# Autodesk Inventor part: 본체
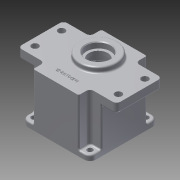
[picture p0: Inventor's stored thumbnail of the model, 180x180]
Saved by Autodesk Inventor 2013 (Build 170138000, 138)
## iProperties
Created: 2015-07
Part Number: 본체
Material: 알루미늄 6061
Document SubType Name: Modeling
Designer: user
Density: 1 g/cm^3
Author: user
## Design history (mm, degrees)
sketch "스케치1"
  geometry: L1 (-45, 45)-(45, 45); L2 (45, 45)-(45, -45); L3 (45, -45)-(-45, -45); L4 (-45, -45)-(-45, 45); 3 further points
  constraints: 8 end point, 2 midpoint, 2 parallel, 1 horizontal, 1 horizontal alignment, 1 perpendicular, 1 vertical alignment
  dimensions: "d0" = 90 distance of L1.start L1.end; "d2" = 90 distance of L1.end L2.end
extrude "돌출1" new body sketch "스케치1" distance "d3" = 7; taper "d4" = 0 deg
sketch "스케치2"
  geometry: L1 (45, 45)-(-45, 45) reference; L2 (-45, 45)-(-45, -45) reference; L3 (-45, -45)-(45, -45) reference; L4 (45, -45)-(45, 45) reference; L5 (-30, 45)-(30, 45); L6 (30, 45)-(30, -45); L7 (30, -45)-(-30, -45); L8 (-30, -45)-(-30, 45); L9 (-45, 30)-(45, 30); L10 (45, 30)-(45, -30); L11 (45, -30)-(-45, -30); L12 (-45, -30)-(-45, 30); 4 further points
  constraints: 16 end point, 4 parallel, 4 point on line, 3 midpoint, 2 horizontal, 2 perpendicular, 2 vertical alignment, 1 horizontal alignment
  dimensions: "d5" = 60 distance of L5.start L5.end; "d7" = 60 distance of L11.end L9.start
extrude "돌출2" join sketch "스케치2" distance "d8" = 63; taper "d9" = 0 deg
sketch "스케치3"
  geometry: L1 (-65, 30)-(65, 30); L2 (65, 30)-(65, -30); L3 (65, -30)-(-65, -30); L4 (-65, -30)-(-65, 30); 3 further points
  constraints: 8 end point, 2 midpoint, 2 parallel, 1 horizontal, 1 horizontal alignment, 1 perpendicular, 1 vertical alignment
  dimensions: "d10" = 60 distance of L3.end L1.start; "d12" = 130 distance of L1.start L1.end
extrude "돌출3" join sketch "스케치3" distance "d13" = 12; taper "d14" = 0 deg
fillet "모깎기1" dims "d15" = 5
sketch "스케치4"
  geometry: L1 (-35, -30)-(-65, -30) reference; L2 (0, 0)-(0, 9.418); L3 (0, 0)-(20.166, 0); C1 r 4.5 at (55, 17.5); C2 r 4.5 at (-55, 17.5); C3 r 4.5 at (-55, -17.5); C4 r 4.5 at (55, -17.5)
  constraints: 4 centre point, 4 end point, 3 symmetric about line, 2 perpendicular, 3 other
  dimensions: "d16" = 9 diameter of C1; "d17" = 110 diameter of C1.centre L2; "d18" = 35 diameter of C1.centre L3
extrude "돌출4" cut sketch "스케치4" distance "d19" = 12; taper "d20" = 0 deg
sketch "스케치5"
  geometry: L1 (45, -45)-(45, 45) reference; L2 (0, 0)-(0, 11.26); L3 (0, 0)-(11.158, 0); C1 r 3.5 at (37, 37); C2 r 3.5 at (-37, 37); C3 r 3.5 at (-37, -37); C4 r 3.5 at (37, -37)
  constraints: 4 centre point, 4 end point, 3 symmetric about line, 1 parallel, 1 perpendicular, 3 other
  dimensions: "d21" = 7 diameter of C1; "d22" = 74 diameter of C1.centre L2; "d23" = 74 diameter of C1.centre L3
extrude "돌출5" cut sketch "스케치5" distance "d24" = 12; taper "d25" = 0 deg
sketch "스케치6"
  geometry: C1 r 40 at (0, 0); 1 further point
  constraints: 1 centre point, 1 coincident
  dimensions: "d26" = 80 diameter of C1
extrude "돌출6" cut sketch "스케치6" distance "d27" = 9; taper "d28" = 0 deg
sketch "스케치7"
  geometry: C1 r 40 at (0, 0) reference; C2 r 39 at (0, 0)
  constraints: 1 centre point, 1 coincident
  dimensions: "d29" = 78 diameter of C2
extrude "돌출7" cut sketch "스케치7" distance "d30" = 52; taper "d31" = 0 deg
sketch "스케치8"
  geometry: L1 (0, 0)-(13.503, 0); L2 (0, 0)-(0, 6.492); L3 (24.749, 24.749)-(-24.749, -24.749); L4 (-24.749, 24.749)-(24.749, -24.749); C1 r 40 at (0, 0) reference; A1 r 39 centre (0, 0) between (21.134, 32.777) and (32.777, 21.134) reference; A2 r 4 centre (24.749, 24.749) between (21.809, 27.462) and (27.462, 21.809); A3 r 3.5 centre (29.836, 19.238) between (32.777, 21.134) and (27.412, 21.762); A4 r 3.5 centre (19.238, 29.836) between (21.762, 27.412) and (21.134, 32.777); 1 further point
  constraints: 10 point on circle, 8 end point, 3 centre point, 3 coincident, 2 midpoint, 2 tangent, 1 horizontal, 1 perpendicular, 1 symmetric about line, 1 other
  dimensions: "d33" = 45 deg angle of L3 L2; "d35" = 45 deg angle of L4 L2; "d37" = 8 diameter of A2; "d38" = 7 diameter of A3
extrude "돌출8" join sketch "스케치8" distance "d39" = 52; taper "d40" = 0 deg
sketch "스케치9"
  geometry: A1 r 39 centre (0, 0) between (-32.777, 21.134) and (-32.777, -21.134) reference; A2 r 39 centre (0, 0) between (-21.134, -32.777) and (21.134, -32.777) reference; A3 r 39 centre (0, 0) between (32.777, -21.134) and (32.777, 21.134) reference; A4 r 20.5 centre (0, 11) between (11.115, -6.225) and (-11.115, -6.225); A5 r 14 centre (0, -20) between (-10.493, -10.732) and (10.493, -10.732); A6 r 3 centre (-12.742, -8.746) between (-10.493, -10.732) and (-11.115, -6.225); A7 r 3 centre (12.742, -8.746) between (11.115, -6.225) and (10.493, -10.732)
  constraints: 8 point on circle, 4 centre point, 4 tangent, 2 vertical alignment
  dimensions: "d44" = 41 diameter of A4; "d45" = 11 distance of A3.centre A4.centre; "d46" = 28 diameter of A5; "d47" = 20 distance of A5.centre A1.centre; "d48" = 6 diameter of A6; "d49" = 6 diameter of A7
extrude "돌출9" join sketch "스케치9" distance "d50" = 7; taper "d51" = 0 deg
sketch "스케치10"
  geometry: C1 r 17.5 at (0, 11); A1 r 20.5 centre (0, 11) between (11.115, -6.225) and (-11.115, -6.225) reference; 1 further point
  constraints: 1 centre point, 1 coincident
  dimensions: "d52" = 35 diameter of C1
extrude "돌출10" cut sketch "스케치10" distance "d53" = 10; taper "d54" = 0 deg
sketch "스케치11"
  geometry: C1 r 17.5 at (0, 0) reference; C2 r 12.5 at (0, 0); 1 further point
  constraints: 1 centre point, 1 coincident
  dimensions: "d55" = 25 diameter of C2
extrude "돌출11" cut sketch "스케치11" distance "d56" = 5; taper "d57" = 0 deg
sketch "스케치12"
  geometry: C1 r 12.5 at (0, 0) reference; C2 r 16 at (0, 0); 1 further point
  constraints: 1 centre point, 1 coincident
  dimensions: "d58" = 32 diameter of C2
extrude "돌출12" cut sketch "스케치12" distance "d59" = 8; taper "d60" = 0 deg
sketch "스케치13"
  geometry: C1 r 11 at (0, -20); A1 r 14 centre (0, -20) between (-10.493, -10.732) and (10.493, -10.732) reference; 1 further point
  constraints: 1 centre point, 1 coincident
  dimensions: "d61" = 22 diameter of C1
extrude "돌출13" cut sketch "스케치13" distance "d62" = 7; taper "d63" = 0 deg
sketch "스케치14"
  geometry: C1 r 11 at (0, 0) reference; C2 r 9.5 at (0, 0); 1 further point
  constraints: 1 centre point, 1 coincident
  dimensions: "d64" = 19 diameter of C2
extrude "돌출14" cut sketch "스케치14" distance "d65" = 1; taper "d66" = 0 deg
sketch "스케치15"
  geometry: C1 r 16 at (0, 11) reference; C2 r 25 at (0, 11); 1 further point
  constraints: 1 centre point, 1 coincident
  dimensions: "d67" = 50 diameter of C2
extrude "돌출15" join sketch "스케치15" distance "d68" = 7; taper "d69" = 0 deg
sketch "스케치16"
  geometry: A1 r 4 centre (24.749, -24.749) between (27.462, -21.809) and (21.809, -27.462) reference; A2 r 4 centre (-24.749, -24.749) between (-21.809, -27.462) and (-27.462, -21.809) reference; A3 r 4 centre (-24.749, 24.749) between (-27.462, 21.809) and (-21.809, 27.462) reference; A4 r 4 centre (24.749, 24.749) between (21.809, 27.462) and (27.462, 21.809) reference; 4 further points
  constraints: 4 coincident
hole "구멍1" sketch "스케치16" at (24.749, 24.749), (24.749, -24.749), (-24.749, -24.749), (-24.749, 24.749) diameter "d70" = 3.459; stored, may be unused: countersink angle "d74" = 90 deg, drill point angle "d76" = 118 deg; dims "d71" = 12, "d72" = 4, "d73" = 2, "d75" = 15
sketch "스케치17"
  geometry: L1 (-30, -45)-(30, -45) reference; 2 further points
  constraints: 1 vertical alignment, 1 other
  dimensions: "d77" = 15 distance from line of L1 point (0, -30)
feature "엠보싱1" sketch "스케치17" dims "d0" = 90, "d2" = 90, "d7" = 60, "d78" = 0.5, "d79" = 0
fillet "모깎기2" dims "d80" = 5
fillet "모깎기3" dims "d81" = 8
fillet "모깎기4" dims "d82" = 0.3
fillet "모깎기5" dims "d83" = 2
chamfer "모따기1" distance "d84" = 1; stored, may be unused: second distance "d85" = 2, angle "d86" = 45 deg
fillet "모깎기6" dims "d87" = 2
fillet "모깎기7" dims "d88" = 2
fillet "모깎기8" dims "d89" = 2
fillet "모깎기9" dims "d90" = 2
node "솔리드1"
pattern_circular "원형 패턴1" dims angle "d42" = 360 deg
